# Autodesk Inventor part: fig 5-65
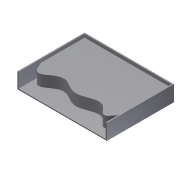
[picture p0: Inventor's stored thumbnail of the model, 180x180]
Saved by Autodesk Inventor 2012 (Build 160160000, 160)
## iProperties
Created: 2004-05
Part Number: fig 5-65
Document SubType Name: Modeling
Designer: CADCIM Technologies
Manufacturer: Standard
Standards Organization: Custom
Density: 1 g/cm^3
Material: Default
Author: CADCIM Technologies
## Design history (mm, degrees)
sketch "Sketch1"
  geometry: L1 (-40, -30)-(40, -30); L2 (40, -30)-(40, 30); L3 (40, 30)-(-40, 30); L4 (-40, 30)-(-40, -30); 1 further point
  constraints: 8 end point, 2 parallel, 1 horizontal, 1 perpendicular, 1 other
  dimensions: "d0" = 80 distance of L1.start L1.end; "d1" = 60 distance of L3.end L1.start; "d2" = 30 distance from line of point (0, 0) L1; "d3" = 40 distance from line of point (0, 0) L4
extrude "Extrusion1" new body sketch "Sketch1" distance "d4" = 14; taper "d5" = 0 deg
shell "Shell1" dims "d6" = 1
workplane "Work Plane1"
sketch "Sketch2"
  geometry: L1 (78, -13)-(78, -11.813); L2 (0, -11.813)-(0, -13); L3 (0, -13)-(78, -13); L4 (0, -11.813)-(17.826, -3.295); L5 (17.826, -3.295)-(60.174, -3.295); L6 (60.174, -3.295)-(78, -11.813); L7 (79, -13.795)-(78, -13.795); L8 (78, 0)-(78, -13) reference; L9 (0, -13)-(0, 0) reference; L10 (78, -13)-(0, -13) reference
  constraints: 14 end point, 3 collinear, 2 equal length, 2 vertical, 1 horizontal alignment, 1 parallel, 1 point on line
extrude "Extrusion2" join sketch "Sketch2" stored distance "d8" = 14; taper "d9" = 0 deg
workplane "Work Plane2"
sketch "Sketch4"
  geometry: 7 further points
  constraints: 7 other
extrude "Extrusion9" join sketch "Sketch4" distance "d35" = 10; taper "d36" = 0 deg
body "Solid1"
other parameters: "d7" = 23, "d18" = 4
